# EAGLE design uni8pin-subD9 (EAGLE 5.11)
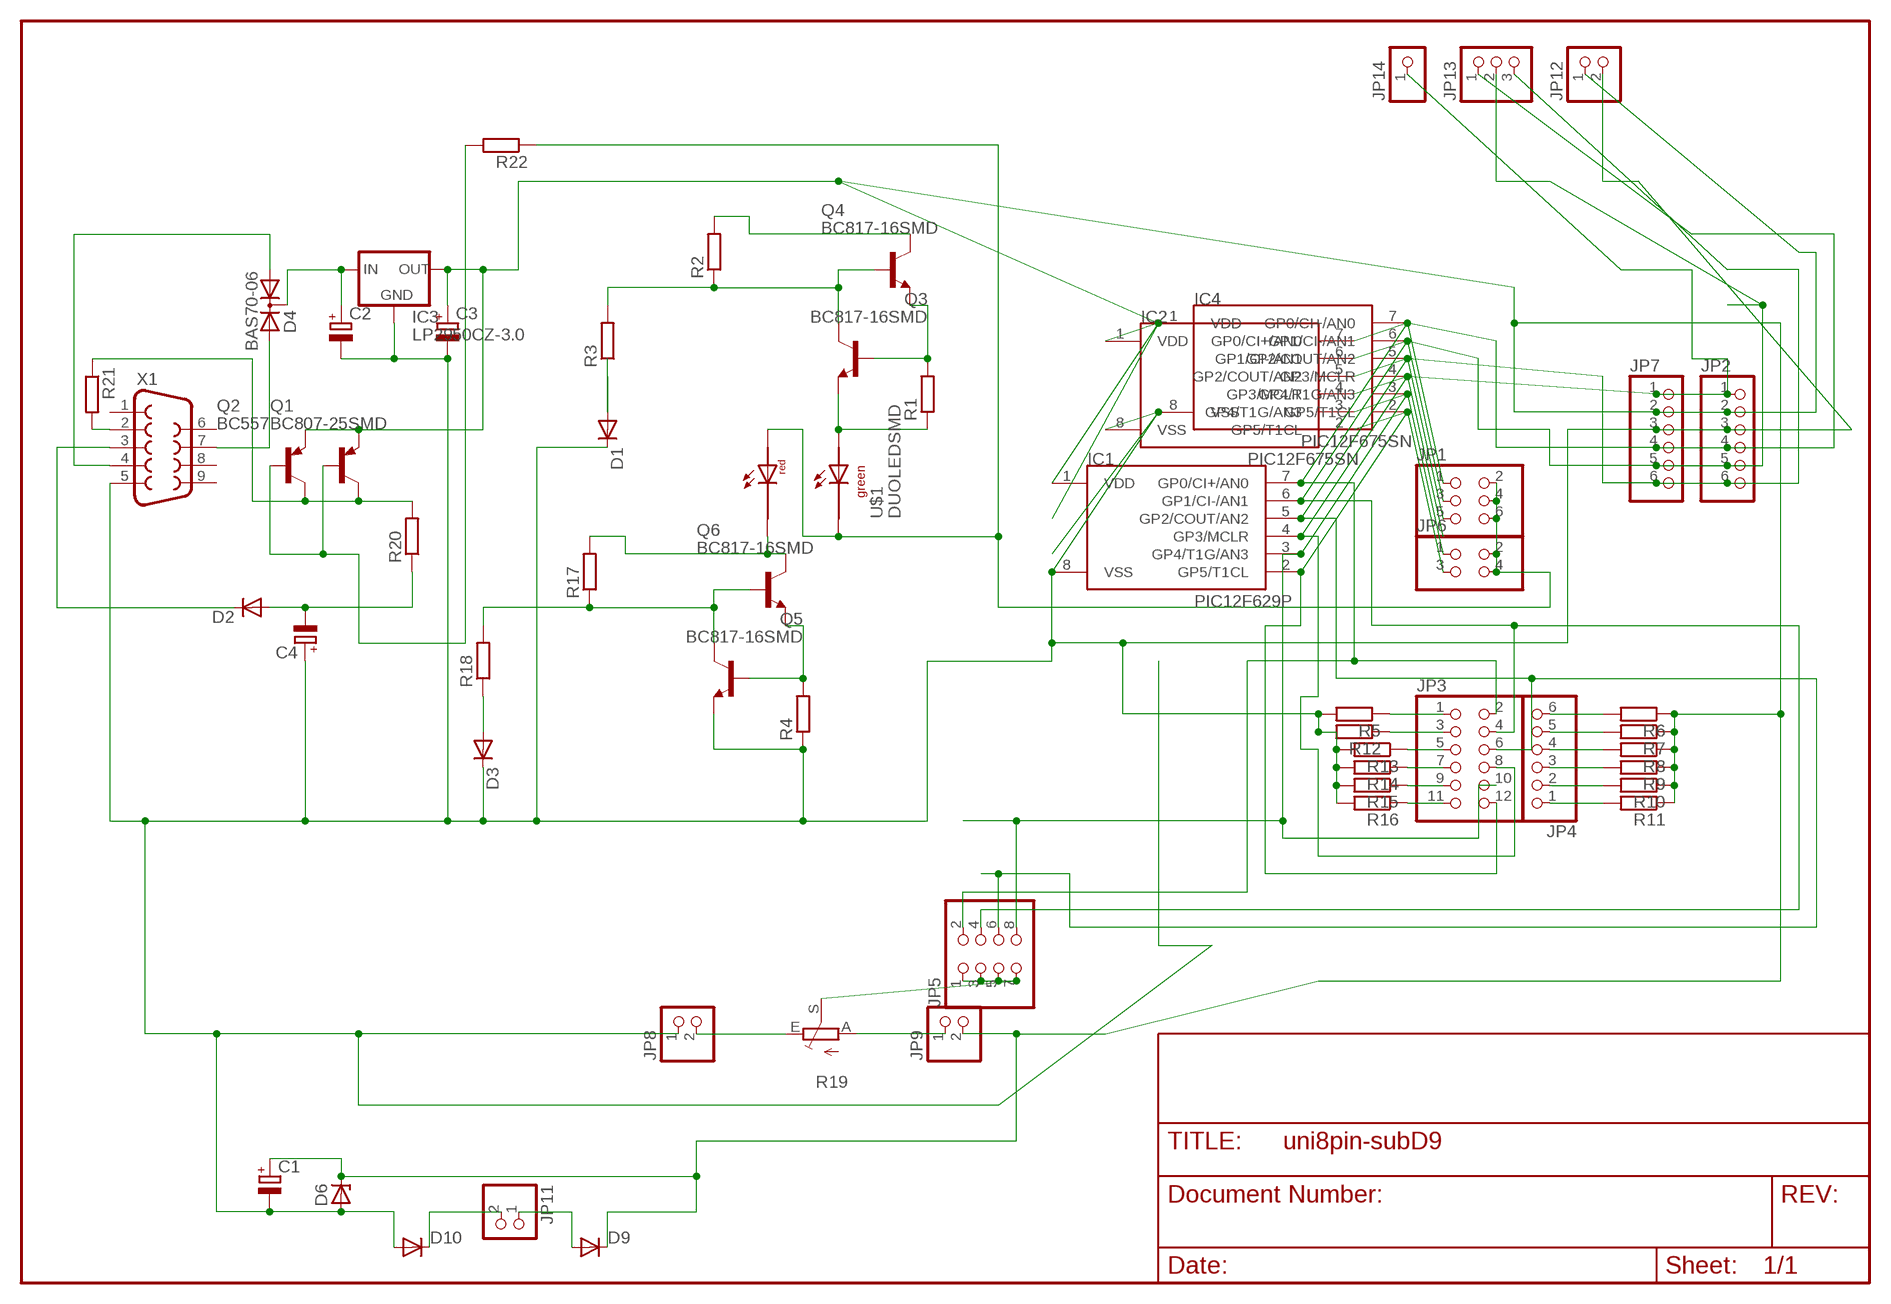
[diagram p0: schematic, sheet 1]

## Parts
C1  CPOL-EU5-13  [2,5-5-FLAT]
C2  CPOL-EUE2-5  [E2-5]
C3  CPOL-EUE2.5-5  [E2,5-5]
C4  CPOL-EUE2.5-5  [E2,5-5]
D1  DIODE-MINIMELF  [MINIMELF]
D2  DIODE-D-5  [D-5]
D3  DIODE-MINIMELF  [MINIMELF]
D4  BAS70-06  [SOT23]
D6  ZENER-DIODEZD-2.5  [ZDIO-2.5]
D9  DIODE-D-5  [D-5]
D10  DIODE-D-5  [D-5]
IC1  PIC12F629P  [DIL8]
IC2  PIC12F675SN  [SO-08]
IC3  LP2950CZ-3.0  [TO92]
IC4  PIC12F675SN  [SO-08]
JP1  PINHD-2X3  [2X03]
JP2  PINHD-1X6  [1X06]
JP3  PINHD-2X6  [2X06]
JP4  PINHD-1X6  [1X06]
JP5  PINHD-2X4  [2X04]
JP6  PINHD-2X2  [2X02]
JP7  PINHD-1X6  [1X06]
JP8  PINHD-1X2  [1X02]
JP9  PINHD-1X2  [1X02]
JP11  PINHD-1X2  [1X02]
JP12  PINHD-1X2  [1X02]
JP13  PINHD-1X3  [1X03]
JP14  PINHD-1X1  [1X01]
Q1  BC807-25SMD  [SOT23-BEC]
Q2  BC557  [TO92-EBC]
Q3  BC817-16SMD  [SOT23-BEC]
Q4  BC817-16SMD  [SOT23-BEC]
Q5  BC817-16SMD  [SOT23-BEC]
Q6  BC817-16SMD  [SOT23-BEC]
R1  R-EU_R1206  [R1206]
R2  R-EU_R1206  [R1206]
R3  R-EU_R1206  [R1206]
R4  R-EU_R1206  [R1206]
R5  R-EU_R1206  [R1206]
R6  R-EU_R1206  [R1206]
R7  R-EU_R1206  [R1206]
R8  R-EU_R1206  [R1206]
R9  R-EU_R1206  [R1206]
R10  R-EU_R1206  [R1206]
R11  R-EU_R1206  [R1206]
R12  R-EU_R1206  [R1206]
R13  R-EU_R1206  [R1206]
R14  R-EU_R1206  [R1206]
R15  R-EU_R1206  [R1206]
R16  R-EU_R1206  [R1206]
R17  R-EU_R1206  [R1206]
R18  R-EU_R1206  [R1206]
R19  TRIM_EU-CA6V  [CA6V]
R20  R-EU_R0805  [R0805]
R21  R-EU_R0805  [R0805]
R22  R-EU_R0805  [R0805]
U$1  DUOLEDSMD  [DUOLEDSMD]
X1  F09H  [F09H]

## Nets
N$1: IC1.3(GP4/T1G/AN3) IC2.3(GP4/T1G/AN3) IC4.3(GP4/T1G/AN3) JP3.10 JP5.8 JP6.1
N$2: Q4.C R2.2
N$3: Q3.E R1.1 U$1.AGRN
N$4: JP1.2 JP1.4 JP1.6 JP6.2 JP6.4 R22.1 U$1.ARED U$1.CGRN
N$5: Q1.B Q2.B R22.2
N$6: Q3.C Q4.B R2.1 R3.2
N$7: Q3.B Q4.E R1.2
N$9: IC1.2(GP5/T1CL) IC2.2(GP5/T1CL) IC4.2(GP5/T1CL) JP3.12 JP6.3
N$10: D1.A R3.1
N$11: IC1.4(GP3/MCLR) IC2.4(GP3/MCLR) IC4.4(GP3/MCLR) JP2.1 JP3.8 JP7.1 JP14.1
N$12: IC1.5(GP2/COUT/AN2) IC2.5(GP2/COUT/AN2) IC4.5(GP2/COUT/AN2) JP1.5 JP2.6 JP3.6 JP5.6 JP7.6 JP13.3
N$13: IC1.6(GP1/CI-/AN1) IC2.6(GP1/CI-/AN1) IC4.6(GP1/CI-/AN1) JP1.3 JP2.5 JP3.4 JP5.4 JP7.5 JP13.2
N$14: IC1.7(GP0/CI+/AN0) IC2.7(GP0/CI+/AN0) IC4.7(GP0/CI+/AN0) JP1.1 JP2.4 JP3.2 JP5.2 JP7.4 JP13.1
N$15: JP4.6 R6.2
N$16: JP5.1 JP5.3 JP5.5 JP5.7 R19.S
N$17: D4.2(A2) X1.7
N$18: JP3.1 R5.1
N$19: D4.1(A1) X1.4
N$20: Q6.C R17.2 U$1.CRED
N$21: JP3.3 R12.1
N$22: JP3.5 R13.1
N$23: JP3.7 R14.1
N$24: JP3.9 R15.1
N$25: JP3.11 R16.1
N$26: JP4.5 R7.2
N$27: JP4.4 R8.2
N$28: JP4.3 R9.2
N$29: JP4.2 R10.2
N$30: JP4.1 R11.2
N$31: JP9.1 R19.A
N$32: JP8.2 R19.E
N$33: D2.C X1.3
N$34: D10.C JP11.2
N$35: D9.A JP11.1
N$36: Q1.C Q2.C R20.2 R21.1
N$37: C4.- D2.A R20.1
N$38: R21.2 X1.2
N$39: Q5.B Q6.E R4.2
N$40: C2.+ D4.3(C) IC3.3(IN)
N$41: Q5.C Q6.B R17.1 R18.2
N$42: D3.A R18.1
VDD: C1.+ C3.+ D6.C D9.C IC1.1(VDD) IC2.1(VDD) IC3.1(OUT) IC4.1(VDD) JP2.2 JP7.2 JP9.2 JP12.1 Q1.E Q2.E R6.1 R7.1 R8.1 R9.1 R10.1 R11.1
VSS: C1.- C2.- C3.- C4.+ D1.C D3.C D6.A D10.A IC1.8(VSS) IC2.8(VSS) IC3.2(GND) IC4.8(VSS) JP2.3 JP7.3 JP8.1 JP12.2 Q5.E R4.1 R5.2 R12.2 R13.2 R14.2 R15.2 R16.2 X1.5
Unconnected: X1.1 X1.6 X1.8 X1.9

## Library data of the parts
C1-C4 = rcl-2:CPOL-EU: POLARIZED CAPACITOR, European symbol
D1 D3 = diode:DIODE-: DIODE
D2 D9 D10 = diode-1:DIODE-: DIODE
D4 = diode-1:BAS70-06: Silicon Schottky Diodes General-purpose diode for high-speed switching
D6 = diode-1:ZENER-DIODE: Z-Diode
IC1 IC2 IC4 = microchip-5:PIC12F6*: uPC nW 1k Program Flash memory 2x Timer Comparator 10b A/D converter/ 4xIN
IC3 = v-reg:LP2950?*: Source: http://cache.national.com/ds/LP/LP2950.pdf
JP1 = pinhead(2):PINHD-2X3: PIN HEADER
JP2 JP7 = pinhead:PINHD-1X6: PIN HEADER
JP3 = pinhead(2):PINHD-2X6: PIN HEADER
JP4 = pinhead(2):PINHD-1X6: PIN HEADER
JP5 = pinhead(2):PINHD-2X4: PIN HEADER
JP6 = pinhead(2):PINHD-2X2: PIN HEADER
JP8 JP9 JP11 = pinhead(2):PINHD-1X2: PIN HEADER
JP12 = pinhead:PINHD-1X2: PIN HEADER
JP13 = pinhead:PINHD-1X3: PIN HEADER
JP14 = pinhead:PINHD-1X1: PIN HEADER
Q1 = transistor-pnp:BC807*: PNP Transistror
Q2 = transistor-pnp:BC557*: PNP Transistror
Q3-Q6 = transistor-npn:BC817*: NPN Transistor
R1-R4 R17 R18 = rcl:R-EU_: RESISTOR, European symbol
R5-R16 R20-R22 = rcl-2:R-EU_: RESISTOR, European symbol
R19 = pot:TRIM_EU-: POTENTIOMETER
U$1 = led:DUOLEDSMD
X1 = con-subd:F09: SUB-D

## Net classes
0 default: width 0.3 mm, drill 0.6 mm, clearance 0.2 mm
1 power: width 0.4 mm, drill 0.6 mm, clearance 0.2 mm

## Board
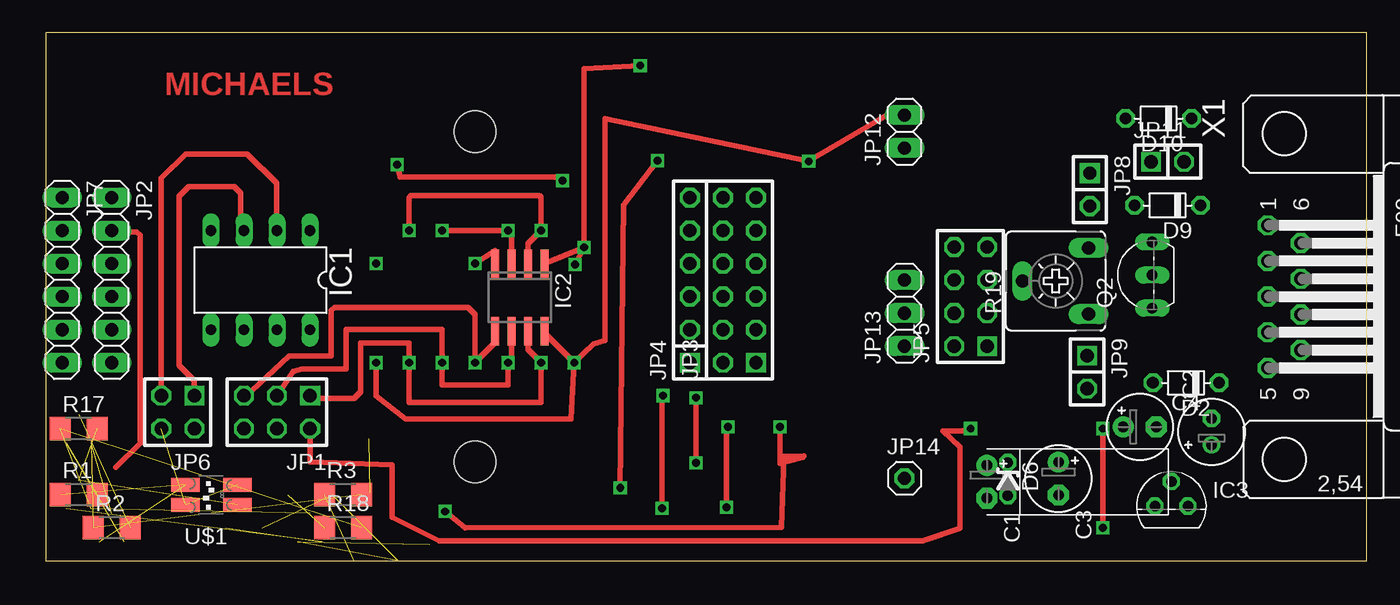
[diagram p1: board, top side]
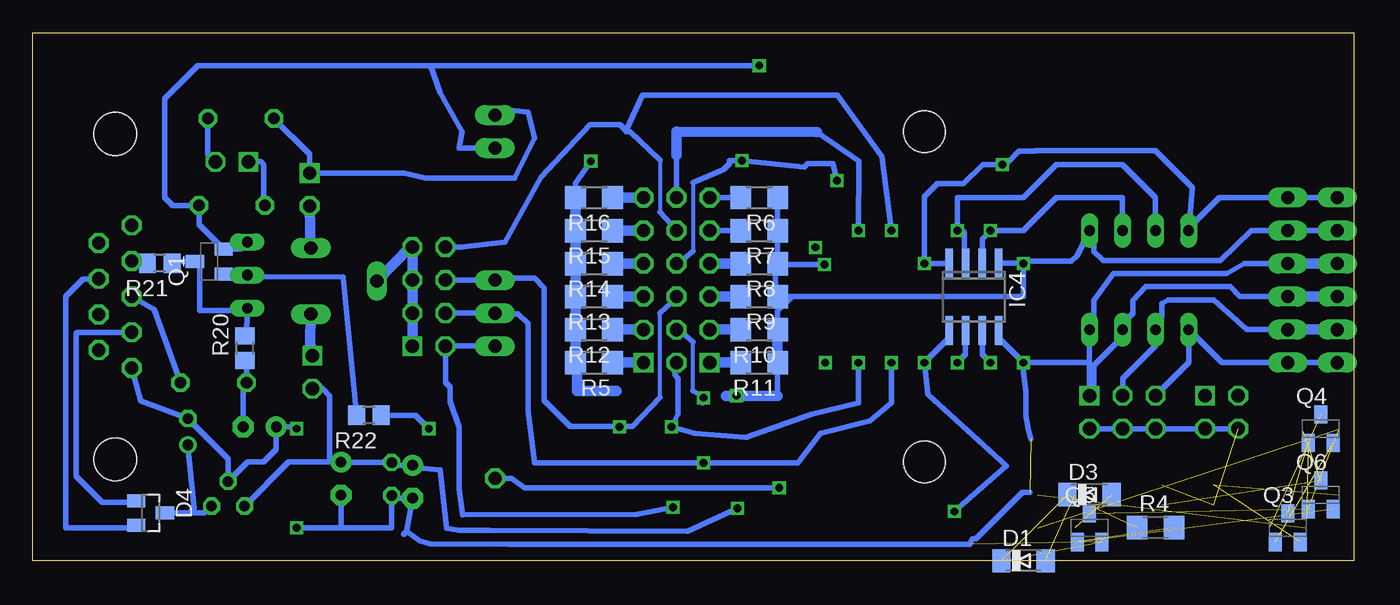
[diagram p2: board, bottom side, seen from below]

Size 101.6 x 40.64 mm. Coordinates in mm from the lower left corner, seen from the top.
Outline: 0,0 101.6,0 101.6,40.64 0,40.64 0,0
Copper layers (1*16): Top 0.035mm / dielectric 1.5mm / Bottom 0.035mm
Design rules "default": minimum track width 10mil, minimum drill 24mil, track to track 8mil, track to pad 8mil, pad to pad 8mil, via to via 8mil, smd to smd 8mil, copper to edge 40mil, drill to drill 8mil, minimum pad ring 10mil, minimum via ring 8mil, stop-mask expansion 4mil, vias tented up to drill 0mil, thermal gap 10mil
Holes 3.2 mm at 33.02,33.02 33.02,7.62

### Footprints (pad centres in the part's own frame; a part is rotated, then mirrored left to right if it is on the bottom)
2,5-5-FLAT = drill 0.813 pad 1.6 round: + -1.27,0 | drill 0.813 pad 1.6 octagon: - 1.27,0
E2-5 = drill 0.813 pad 1.27 round: + -1.016,0 | drill 0.813 pad 1.27 octagon: - 1.016,0
E2,5-5 = drill 0.813 pad 1.6 round: + -1.27,0 | drill 0.813 pad 1.6 octagon: - 1.27,0
MINIMELF = smd 1.4 x 1.8: A 1.7,0; C -1.7,0
D-5 = drill 0.9 octagon: A 2.54,0; C -2.54,0
SOT23 = smd 1 x 1.4: 1 -0.95,-1.1; 2 0.95,-1.1; 3 0,1.1
ZDIO-2.5 = drill 0.813 octagon: A 1.27,0; C -1.27,0
DIL8 = drill 0.813 long: 1 -3.81,-3.81; 2 -1.27,-3.81; 3 1.27,-3.81; 4 3.81,-3.81; 5 3.81,3.81; 6 1.27,3.81; 7 -1.27,3.81; 8 -3.81,3.81
SO-08 = smd 0.6 x 2.2: 1 -1.905,-2.6; 2 -0.635,-2.6; 3 0.635,-2.6; 4 1.905,-2.6; 5 1.905,2.6; 6 0.635,2.6; 7 -0.635,2.6; 8 -1.905,2.6
TO92 = drill 0.813 octagon: 1 -1.27,0; 2 0,1.905; 3 1.27,0
2X03 = drill 1.016 square: 1 -2.54,-1.27 | drill 1.016 octagon: 2 -2.54,1.27; 3 0,-1.27; 4 0,1.27; 5 2.54,-1.27; 6 2.54,1.27
1X06 = drill 1.016 long: 1 -6.35,0; 2 -3.81,0; 3 -1.27,0; 4 1.27,0; 5 3.81,0; 6 6.35,0
2X06 = drill 1.016 square: 1 -6.35,-1.27 | drill 1.016 octagon: 2 -6.35,1.27; 3 -3.81,-1.27; 4 -3.81,1.27; 5 -1.27,-1.27; 6 -1.27,1.27; 7 1.27,-1.27; 8 1.27,1.27; 9 3.81,-1.27; 10 3.81,1.27; 11 6.35,-1.27; 12 6.35,1.27
1X06' = drill 1.016 square: 1 -6.35,0 | drill 1.016 octagon: 2 -3.81,0; 3 -1.27,0; 4 1.27,0; 5 3.81,0; 6 6.35,0
2X04 = drill 1.016 square: 1 -3.81,-1.27 | drill 1.016 octagon: 2 -3.81,1.27; 3 -1.27,-1.27; 4 -1.27,1.27; 5 1.27,-1.27; 6 1.27,1.27; 7 3.81,-1.27; 8 3.81,1.27
2X02 = drill 1.016 square: 1 -1.27,-1.27 | drill 1.016 octagon: 2 -1.27,1.27; 3 1.27,-1.27; 4 1.27,1.27
1X02 = drill 1.016 square: 1 -1.27,0 | drill 1.016 octagon: 2 1.27,0
1X02' = drill 1.016 long: 1 -1.27,0; 2 1.27,0
1X03 = drill 1.016 long: 1 -2.54,0; 2 0,0; 3 2.54,0
1X01 = drill 1.016 octagon: 1 0,0
SOT23-BEC = smd 1 x 1.4: B -0.95,-1.1; C 0,1.1; E 0.95,-1.1
TO92-EBC = drill 0.813 long: B 0,-1.27; C -2.54,-1.27; E 2.54,-1.27
R1206 = smd 1.6 x 1.803: 1 -1.422,0; 2 1.422,0
CA6V = drill 1.016 long: A -2.54,-2.54; E 2.54,-2.54; S 0,2.54
R0805 = smd 1.3 x 1.5: 1 -0.95,0; 2 0.95,0
DUOLEDSMD = smd 1.067 x 2.184: AGRN 0.77,1.95; ARED -0.77,1.95; CGRN 0.77,-2.05; CRED -0.77,-2.05
F09H = drill 1.016 octagon: 1 -5.486,-1.27; 2 -2.743,-1.27; 3 0,-1.27; 4 2.743,-1.27; 5 5.486,-1.27; 6 -4.115,1.27; 7 -1.372,1.27; 8 1.372,1.27; 9 4.115,1.27 | hole 3.302: -12.522,0; 12.522,0

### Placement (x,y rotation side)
C1  72.37,6.08 270 top
C2  89.65,9.93 90 top
C3  77.88,6.32 270 top
C4  84.13,10.3 0 top
D1  25.4,0 0 bottom
D2  87.68,13.69 180 top
D3  20.32,5.08 0 bottom
D4  92.52,3.67 270 bottom
D6  73.98,6.29 270 top
D9  86.26,27.34 180 top
D10  85.58,34.03 180 top
IC1  16.51,21.59 180 top
IC2  36.46,20.26 180 top
IC3  86.56,4.2 0 top
IC4  29.21,20.32 180 bottom
JP1  17.78,11.43 180 top
JP2  5.08,21.59 270 top
JP3  53.34,21.59 90 top
JP4  [1X06']  49.53,21.59 90 top
JP5  71.12,20.32 90 top
JP6  10.16,11.43 180 top
JP7  1.27,21.59 270 top
JP8  80.3,28.56 270 top
JP9  80.08,14.51 270 top
JP11  86.27,30.69 0 top
JP12  [1X02']  66.04,33.02 90 top
JP13  66.04,19.05 90 top
JP14  66.04,6.35 0 top
Q1  88.01,23.02 90 bottom
Q2  83.82,21.98 90 top
Q3  5.08,2.54 0 bottom
Q4  2.54,10.16 0 bottom
Q5  20.32,2.54 0 bottom
Q6  2.54,5.08 0 bottom
R1  2.54,5.08 0 top
R2  5.08,2.54 0 top
R3  22.86,5.08 0 top
R4  15.24,2.54 0 bottom
R5  58.42,15.24 180 bottom
R6  45.72,27.94 180 bottom
R7  45.72,25.4 180 bottom
R8  45.72,22.86 180 bottom
R9  45.72,20.32 180 bottom
R10  45.72,17.78 180 bottom
R11  45.72,15.24 180 bottom
R12  58.42,17.78 180 bottom
R13  58.42,20.32 180 bottom
R14  58.42,22.86 180 bottom
R15  58.42,25.4 180 bottom
R16  58.42,27.94 180 bottom
R17  2.54,10.16 0 top
R18  22.86,2.54 0 top
R19  77.66,21.52 90 top
R20  85.26,16.35 90 bottom
R21  91.81,22.9 180 bottom
R22  75.73,11.19 180 bottom
U$1  12.7,5.08 90 top
X1  95.25,20.32 270 top

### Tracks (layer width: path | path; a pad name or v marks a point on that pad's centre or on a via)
N$1  (via drill 0.6)
  Top 0.406: JP6.1 11.43,13.86 10.25,15.04 10.25,28.04 11,28.79 14.5,28.79 15,28.29 15,25.79 14.97,25.82 IC1.3 | IC2.3 35.83,25.14 v35.56,25.4 v30.48,25.4
  Bottom 0.305: 53.34,30.83 53.34,26.83
  Bottom 0.406: 53.34,30.83 55.65,33.02 55.96,33.02 55.96,33.08 | JP3.10 52.07,25.44 53.34,26.83 | v35.56,25.4 36.27,31.1 39.71,35.83 54.71,35.83 55.96,33.08 | IC1.3 15.24,27.94 17.78,30.48 22.86,30.48 25.4,27.94 30.48,27.94 v30.48,25.4 30.11,25.4 29.96,25.25 29.96,23.04 IC4.3 | JP5.8 68.62,24.13 65.25,24.5 62.5,29.5 58.71,33.54 56.42,33.54 55.96,33.08
N$2  (1 unrouted)
N$3  (2 unrouted)
N$4  (via drill 0.6)  (2 unrouted)
  Top 0.406: JP1.2 20.32,7.62 26.65,7.37 26.65,3.33 30.23,1.54 67.46,1.54 70.29,2.5 70.29,8.75 69,10 70.96,10 v71.12,10.16
  Bottom 0.406: R22.1 72.15,11.19 v71.12,10.16 | JP1.6 15.06,9.98 | JP1.6 JP1.4 JP1.2 | JP6.4 JP6.2 JP1.6
N$5
  Bottom 0.406: R22.2 77.71,21.83 84.07,21.86 85.75,21.86 | 85.75,21.86 Q2.B | Q1.B 85.96,22.07 85.75,21.86
N$6  (3 unrouted)
N$7  (2 unrouted)
N$9  (via drill 0.6)
  Top 0.406: IC2.2 37.09,24.39 v38.1,25.4 38.1,27.94 | JP6.3 8.89,29.43 10.75,31.29 15.5,31.29 17.75,29.04 17.75,26.54 18,26.29 17.51,25.8 | 17.51,25.8 17.5,25.79 | 17.51,25.8 IC1.2 | 38.04,28.04 38.1,27.98 38.1,27.94 | v27.94,25.4 27.94,27.94 28.08,28.08 37.95,28.08 38.08,27.94 38.1,27.94
  Bottom 0.406: v38.1,25.4 38.06,30.73 41.27,32.98 | 52.07,31.22 JP3.12 | IC4.2 28.57,24.77 v27.94,25.4 25.4,25.4 22.86,27.94 17.78,27.94 IC1.2
  Bottom 0.813: 41.27,32.98 52.07,33.02 52.07,31.22
N$10  (1 unrouted)
N$11  (via drill 0.6)
  Top 0.406: IC2.4 34.55,23.86 v33.02,22.86 | v44.18,5.62 44.43,27.36 v47.04,30.79 | v39.75,29.25 39.25,29.5 27.25,29.5 v27.02,30.48
  Bottom 0.305: 50.8,29.08 50.8,23.83
  Bottom 0.406: 12.43,25.86 12.5,25.79 | 12.43,25.86 IC1.4 12.43,28.72 15.25,31.54 24.46,31.54 24.5,31.5 25.75,31.5 26.77,30.48 v27.02,30.48 28.52,30.48 30,29 32,29 33,28 33,22.88 v33.02,22.86 31.18,22.86 IC4.4 | 12.43,25.86 10.35,27.94 JP2.1 JP7.1 | JP3.8 51.93,22.86 50.8,23.83 | 50.8,29.08 48.46,30.08 48,30.54 48,30.79 v47.04,30.79 42.25,30.29 42,30.54 40.04,30.54 v39.75,29.25 | JP14.1 64.77,6.35 63.75,5.62 v44.18,5.62
N$12  (via drill 0.6)
  Top 0.406: IC2.5 34.55,16.77 v33.02,15.24 | 33.04,15.04 33.02,15.06 v33.02,15.24 | 56.75,8.02 56.58,2.58 32.25,2.54 v30.71,3.79 | 56.75,8.02 58.29,8.08 | v33.02,15.24 33.02,18.94 32.46,19.5 22.21,19.5 21.96,19.25 21.96,15.75 18.71,15.75 15.25,12.54 15.24,12.54 JP1.5 | v56.46,10.29 56.46,7.48 58.22,7.97 58.22,7.99 56.75,8.02
  Bottom 0.305: 53.34,12.58 53.34,19.08
  Bottom 0.406: 56.42,10.33 60.25,10.33 62.25,12.33 62.25,21 63,21.75 65.88,21.75 JP13.3 JP5.6 | 53.34,12.58 55.46,10.33 56.42,10.33 | v30.71,3.79 26.71,7.29 32.73,12.79 v33.02,15.24 31.11,17.14 IC4.5 | JP3.6 52.07,20.22 53.34,19.08 | JP7.6 JP2.6 10.16,15.24 IC1.5 12.7,15.24 JP1.5 | 56.42,10.33 v56.46,10.29
N$13  (via drill 0.6)
  Top 0.406: IC2.6 35.83,15.51 v35.56,15.24 35.59,15.24 35.79,15.04 35.54,14.79 35.54,13.54 30.48,13.54 v30.48,15.24 30.48,17.78 23.11,17.78 23.11,14.74 19.7,14.74 19.03,14.57 JP1.3 | v50,7.54 v50,12.54
  Bottom 0.305: 50.8,13.08 50.8,16.83
  Bottom 0.406: JP2.5 8.24,17.78 10.75,20.07 14.25,20.07 14.75,19.79 14.75,18.79 15.13,18.41 | 15.13,18.41 15.25,18.29 15.25,16.54 17.75,14.04 17.75,12.54 17.78,12.57 JP1.3 | 15.13,18.41 IC1.6 | 52.07,17.44 JP3.4 52.01,17.78 51.96,17.83 50.8,16.83 | IC4.6 29.84,15.88 v30.48,15.24 | 50.8,13.08 50.05,12.63 50.09,12.13 v50,12.54 | 35.83,15.51 v35.56,15.24 35.56,12.16 37.22,10.75 41,9.79 42.75,7.54 v50,7.54 63,7.54 63.5,11.54 63.5,18.25 64.25,19 65.99,19 JP13.2 | JP13.2 JP5.4 | 64.75,19.25 65.84,19.25 JP13.2
  Bottom 0.813: JP7.5 JP2.5
N$14  (via drill 0.6)
  Top 0.406: IC2.7 37.09,16.25 v38.1,15.24 v38.1,15.23 38.29,15.04 38.1,14.85 | 38.1,14.85 38.04,14.79 | 38.1,14.85 38.1,12.2 27.94,12.2 v27.94,15.24 27.94,16.73 27.96,16.75 24.21,16.75 24.21,13 23.71,12.5 20.52,12.5 JP1.1 | v52.34,4.12 52.34,9.7 52.3,10.45 v52.46,10.29
  Bottom 0.406: JP2.4 8.78,20.32 9.5,21.08 16,21.08 17,20.04 17,19.04 17.51,18.53 IC1.7 17.51,17.53 20,15.04 20,13.04 20.32,12.72 JP1.1 | IC4.7 28.57,15.88 v27.94,15.24 | v52.34,4.12 55.13,3.58 68.54,3.55 68.79,5.54 68.79,10.29 69.5,12.25 69.5,13.37 69.85,13.72 JP5.2 JP13.1 | 52.21,15.1 52.21,14.29 51.96,14.04 51.96,11.29 v52.46,10.29 50.67,9.79 46.75,9.5 41.75,11.25 38.1,12.15 v38.1,15.24
  Bottom 0.813: JP7.4 JP2.4 | 52.21,15.1 JP3.2
N$15
  Bottom 0.406: R6.2 47.14,27.9 47.21,27.83 47.32,27.94 JP4.6
N$16
  Bottom 0.813: R19.S 72.58,24.13 JP5.7 JP5.5 JP5.3 JP5.1
N$17
  Bottom 0.406: X1.7 97.69,21.69 99.06,20.32 99.06,2.54 93.8,2.54 D4.2
N$18
  Bottom 0.813: JP3.1 R5.1
N$19
  Bottom 0.406: X1.4 98.17,17.58 98.25,17.5 98.25,6.5 96.25,4.5 93.74,4.5 D4.1
N$20  (2 unrouted)
N$21
  Bottom 0.813: JP3.3 R12.1
N$22
  Bottom 0.813: JP3.5 R13.1
N$23
  Bottom 0.813: JP3.7 R14.1
N$24
  Bottom 0.813: JP3.9 R15.1
N$25
  Bottom 0.813: JP3.11 R16.1
N$26
  Bottom 0.406: R7.2 47.39,25.4 47.46,25.33 47.53,25.4 JP4.5
N$27
  Bottom 0.813: R8.2 JP4.4
N$28
  Bottom 0.813: R9.2 JP4.3
N$29
  Bottom 0.813: R10.2 JP4.2
N$30
  Bottom 0.813: R11.2 JP4.1
N$31
  Bottom 0.813: JP9.1 80.24,16.69 R19.A
N$32
  Bottom 0.813: JP8.2 80.26,25.56 R19.E
N$33
  Bottom 0.406: X1.3 92.25,19.32 D2.C
N$34
  Bottom 0.406: D10.C 88.12,31.27 JP11.2
N$35
  Bottom 0.406: JP11.1 84.03,30.69 83.82,30.48 83.82,27.44 D9.A
N$36
  Bottom 0.406: R20.2 85.09,18.41 Q2.C 85.09,19.25 88.75,19.25 88.75,23.02 Q1.C 90.74,23.02 R21.1
N$37
  Bottom 0.406: C4.- 85.4,13.43 D2.A 85.14,15.28 R20.1
N$38
  Bottom 0.406: X1.2 92.31,23.06 R21.2
N$39  (2 unrouted)
N$40
  Bottom 0.406: 89.5,3.67 88.36,3.67 IC3.3 | 89.5,3.67 D4.3 | C2.+ 89.15,4.02 89.5,3.67
N$41  (3 unrouted)
N$42  (1 unrouted)
VDD  (via drill 0.6)
  Top 0.406: 38.37,23.12 IC2.1 v41.39,24.11 | 5.39,7.18 7.25,9.04 7.25,25.04 7,25.29 5,25.29 | 5,25.29 4.75,25.29 4.5,25.54 4.75,25.54 5,25.29 | 5,25.29 5.08,25.37 JP2.2 | v41.39,24.11 41.39,37.85 v45.72,38.1 | v40.71,22.79 v41.39,24.11 | v47.38,4.04 47.38,12.45 v47.46,12.7
  Bottom 0.406: 44.45,20.32 44.46,20.33 | 44.45,20.32 R9.1 43.18,20.32 | JP7.2 JP2.2 7.89,25.4 10.25,23.11 19.25,23.11 20,23.79 20,25.54 20.25,25.79 20.05,25.99 IC1.1 21.26,23.49 21.71,23.04 25.4,23.04 v25.4,22.86 | IC4.1 25.46,22.92 v25.4,22.86 | v47.38,4.04 51.25,2.28 66.5,2.33 68.75,2.33 69.75,2.5 70.25,7 71.6,7.1 C1.+ 73.77,7.35 D6.C 77.88,7.56 C3.+ 78.74,7.59 | 78.74,7.59 81.9,7.59 IC3.1 | v45.72,38.1 71,38.1 | 71,38.1 88.9,38.1 91.44,35.56 91.44,27.94 90.84,27.34 D9.C 88.8,25.86 Q1.E 85.64,23.97 Q2.E | JP9.2 79.28,13.24 78.74,12.7 78.74,7.59 | JP12.1 68.79,31.73 68.58,33.02 70.25,36 71,38.1 | v25.4,22.86 25.4,20.32 43.18,20.32 | v40.71,22.79 44.3,22.79 R8.1 | R11.1 44.3,12.7 | R10.1 44.3,19.2 43.18,20.32 | 44.45,20.32 44.45,22.71 R8.1 | R8.1 R7.1 R6.1
  Bottom 0.813: 44.3,12.7 v47.46,12.7 48.26,12.7 | R10.1 R11.1
VSS  (via drill 0.6)  (5 unrouted)
  Top 0.406: IC2.8 38.37,17.52 v40.64,15.24 | v40.64,15.24 42.14,16.69 43,16.94 43,34 v58.67,30.73 64.89,34.41 65.92,34.41 JP12.2 | v25.4,15.24 25.4,12.7 27.69,10.91 40.39,10.91 v40.64,15.24 | v81.28,2.54 v81.28,10.16
  Bottom 0.406: JP2.3 8.43,22.86 9.75,22.1 18.5,22.1 20,20.04 20,18.1 IC1.8 20.32,15.24 | 40.54,15.29 40.59,15.24 v40.64,15.24 | R16.2 59.84,29.06 v58.67,30.73 | IC4.8 27.3,17.14 v25.4,15.24 | 20.32,15.24 20.32,13.1 | 20.32,15.24 v25.4,15.24 | 72.84,2.28 71.85,1.54 71.04,1.29 65,1.27 29.5,1.27 29.32,1.68 29.07,1.68 25.5,5.25 24.89,5.25 | 72.84,2.28 C1.- 73.77,4.81 D6.A 73.98,2.54 77.88,2.54 | v25.4,15.24 25.4,14.56 25.21,13 25.21,11.14 25.03,10.07 24.85,9.39 | 72.84,2.28 73.08,2.04 | X1.5 93.29,12.29 C2.- 86.56,7.86 IC3.2 85.05,7.62 83.82,7.62 82.86,8.58 C4.+ 81.28,10.3 v81.28,10.16 | 77.88,2.54 v81.28,2.54 | 77.88,2.54 C3.- | D10.A 80.3,31.29 JP8.1 73.01,29.83 71.37,29.44 64.54,29.44 63,32.52 63.5,34.5 65.58,34.75 JP12.2
  Bottom 0.813: JP7.3 JP2.3 | 56.71,13.08 59.71,13.08 59.71,15.24 R5.2 R12.2 R13.2 R14.2 R15.2 R16.2

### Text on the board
Top: MICHAELS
